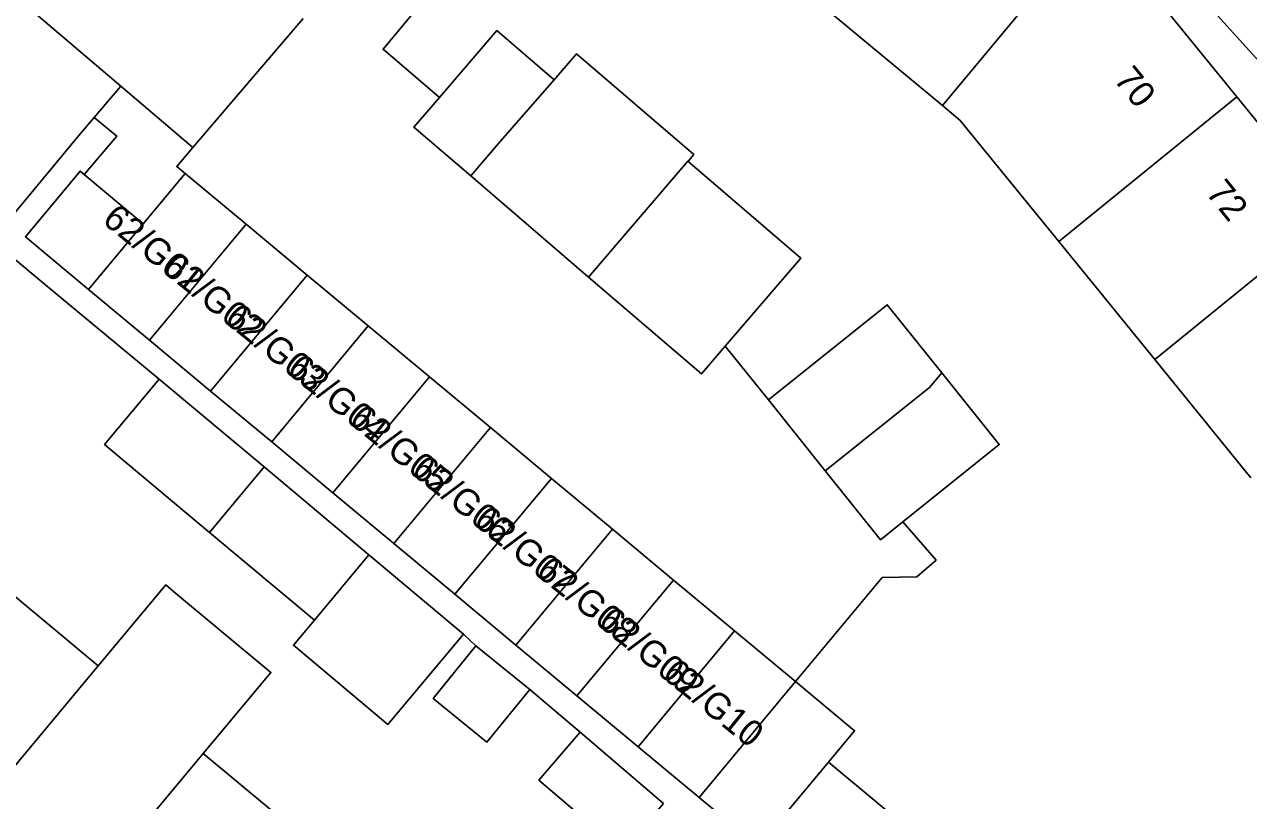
# Model space of a CAD drawing. Extents: x 162074 to 163034, y 381824 to 382557.
# Drawn here: x 162432.01 to 162478.91, y 381913.94 to 381943.68 of the extents above; entities that cross this region are included whole.
import ezdxf

# ---------------------------------------------------------------- set-up
doc = ezdxf.new("R2010")
doc.units = 0
for name, color, linetype in [('IMGEO_Pand', 7, 'Continuous'), ('IMGEO_Pand_nummerreeks', 7, 'Continuous'), ('IMGEO_Rijbaan_lokaal_open', 7, 'Continuous'), ('IMGEO_Voetpad_open', 7, 'Continuous')]:
    doc.layers.add(name, color=color, linetype=linetype)

msp = doc.modelspace()

# ---------------------------------------------------------------- linework, layer by layer
at = {"layer": 'IMGEO_Pand'}
for points in [[(162435.703, 381941.319), (162431.774, 381944.667), (162435.925, 381949.539)], [(162467.176, 381940.577), (162472.75, 381947.274)], [(162472.75, 381947.274), (162475.216, 381945.222), (162475.088, 381945.068), (162478.463, 381940.914)], [(162467.176, 381940.577), (162462.557, 381944.412)], [(162442.682, 381943.917), (162438.464, 381938.967)], [(162447.904, 381940.882), (162450.107, 381943.449), (162452.304, 381941.563)], [(162452.304, 381941.563), (162453.157, 381942.556), (162457.651, 381938.699), (162457.446, 381938.46), (162457.429, 381938.44)], [(162449.107, 381937.877), (162450.237, 381939.193), (162452.304, 381941.563)], [(162435.703, 381941.319), (162434.676, 381940.113)], [(162438.464, 381938.967), (162436.557, 381940.591), (162435.703, 381941.319)], [(162449.107, 381937.877), (162446.929, 381939.746), (162447.904, 381940.882)], [(162471.634, 381935.364), (162467.861, 381940.008), (162467.176, 381940.577)], [(162471.634, 381935.364), (162478.463, 381940.914)], [(162478.463, 381940.914), (162482.143, 381936.385)], [(162434.676, 381940.113), (162435.54, 381939.396), (162434.293, 381937.933)], [(162438.163, 381937.971), (162437.843, 381938.238), (162438.464, 381938.967)], [(162457.429, 381938.44), (162453.619, 381934.004)], [(162457.429, 381938.44), (162461.753, 381934.728), (162458.86, 381931.358)], [(162434.463, 381933.527), (162432.041, 381935.544), (162434.138, 381938.062), (162434.293, 381937.933)], [(162434.293, 381937.933), (162436.56, 381936.045)], [(162436.56, 381936.045), (162438.163, 381937.971)], [(162438.163, 381937.971), (162440.502, 381936.023)], [(162453.619, 381934.004), (162449.107, 381937.877)], [(162482.143, 381936.385), (162475.314, 381930.836)], [(162434.463, 381933.527), (162436.56, 381936.045)], [(162440.502, 381936.023), (162436.802, 381931.579)], [(162442.841, 381934.076), (162440.502, 381936.023)], [(162475.314, 381930.836), (162471.634, 381935.364)], [(162442.841, 381934.076), (162439.141, 381929.632)], [(162445.181, 381932.128), (162442.841, 381934.076)], [(162458.86, 381931.358), (162457.944, 381930.291), (162453.619, 381934.004)], [(162436.802, 381931.579), (162434.463, 381933.527)], [(162460.512, 381929.294), (162465.067, 381932.939), (162467.15, 381930.336)], [(162441.481, 381927.684), (162445.181, 381932.128)], [(162447.52, 381930.181), (162445.181, 381932.128)], [(162439.141, 381929.632), (162436.802, 381931.579)], [(162478.994, 381926.306), (162475.314, 381930.836)], [(162443.82, 381925.737), (162447.52, 381930.181)], [(162449.859, 381928.233), (162447.52, 381930.181)], [(162467.15, 381930.336), (162466.688, 381929.77), (162462.691, 381926.571)], [(162467.15, 381930.336), (162469.356, 381927.58), (162465.664, 381924.626)], [(162439.098, 381924.216), (162435.075, 381927.588), (162437.172, 381930.09)], [(162437.172, 381930.09), (162441.188, 381926.723)], [(162441.481, 381927.684), (162439.141, 381929.632)], [(162462.691, 381926.571), (162460.512, 381929.294)], [(162446.159, 381923.789), (162449.859, 381928.233)], [(162452.198, 381926.285), (162449.859, 381928.233)], [(162443.82, 381925.737), (162441.481, 381927.684)], [(162441.188, 381926.723), (162439.098, 381924.216)], [(162441.188, 381926.723), (162445.204, 381923.357)], [(162465.664, 381924.626), (162464.801, 381923.935), (162462.691, 381926.571)], [(162452.198, 381926.285), (162448.498, 381921.842)], [(162454.537, 381924.338), (162452.198, 381926.285)], [(162446.159, 381923.789), (162443.82, 381925.737)], [(162443.114, 381920.85), (162439.098, 381924.216)], [(162450.838, 381919.894), (162454.537, 381924.338)], [(162454.537, 381924.338), (162456.877, 381922.39)], [(162448.498, 381921.842), (162446.159, 381923.789)], [(162445.204, 381923.357), (162443.114, 381920.85)], [(162445.204, 381923.357), (162448.831, 381920.317)], [(162427.54, 381918.534), (162430.803, 381922.449), (162434.83, 381919.095)], [(162434.83, 381919.095), (162437.421, 381922.203), (162437.718, 381921.955), (162441.447, 381918.85), (162439.247, 381916.212), (162438.856, 381915.742)], [(162456.877, 381922.39), (162453.177, 381917.947)], [(162459.216, 381920.443), (162456.877, 381922.39)], [(162450.838, 381919.894), (162448.498, 381921.842)], [(162448.831, 381920.317), (162445.931, 381916.857), (162442.313, 381919.889), (162443.114, 381920.85)], [(162455.516, 381915.999), (162459.216, 381920.443)], [(162459.216, 381920.443), (162461.555, 381918.495)], [(162451.365, 381918.198), (162449.724, 381916.179), (162447.663, 381917.854), (162449.304, 381919.873)], [(162449.304, 381919.873), (162451.365, 381918.198)], [(162453.177, 381917.947), (162450.838, 381919.894)], [(162434.83, 381919.095), (162425.697, 381908.139)], [(162461.555, 381918.495), (162457.856, 381914.051)], [(162461.555, 381918.495), (162463.814, 381916.614), (162462.808, 381915.405)], [(162455.516, 381915.999), (162453.177, 381917.947)], [(162456.497, 381913.825), (162454.922, 381911.982), (162451.718, 381914.721), (162453.293, 381916.563)], [(162453.293, 381916.563), (162456.497, 381913.825)], [(162430.021, 381905.142), (162438.856, 381915.742)], [(162438.856, 381915.742), (162442.882, 381912.389), (162441.973, 381911.298)], [(162457.856, 381914.051), (162455.516, 381915.999)], [(162460.871, 381913.079), (162462.808, 381915.405)], [(162462.808, 381915.405), (162468.748, 381910.459)], [(162460.699, 381912.872), (162460.115, 381912.17), (162457.856, 381914.051)]]:
    msp.add_lwpolyline(points, dxfattribs=at)
at = {"layer": 'IMGEO_Rijbaan_lokaal_open'}
for points in [[(162453.434, 381951.988), (162445.748, 381942.733), (162447.904, 381940.882)], [(162458.86, 381931.358), (162460.512, 381929.294)], [(162465.664, 381924.626), (162466.937, 381923.157), (162466.195, 381922.514), (162464.872, 381922.48), (162461.555, 381918.495)]]:
    msp.add_lwpolyline(points, dxfattribs=at)
msp.add_arc((162415.641, 381887.258), 86.754, 39.9668, 48.2971, dxfattribs=at)
at = {"layer": 'IMGEO_Voetpad_open'}
for points in [[(162524.728, 381886.592), (162523.779, 381887.754), (162520.879, 381891.323), (162500, 381916.926), (162479.554, 381941.998), (162475.997, 381945.948)], [(162420.235, 381945.27), (162427.488, 381939.257), (162431.316, 381936.081), (162434.157, 381939.504), (162434.676, 381940.113)], [(162429.113, 381936.789), (162433.138, 381933.434), (162437.172, 381930.09)], [(162448.831, 381920.317), (162449.304, 381919.873)], [(162451.365, 381918.198), (162453.293, 381916.563)]]:
    msp.add_lwpolyline(points, dxfattribs=at)

# ---------------------------------------------------------------- texts
at = {"layer": 'IMGEO_Pand_nummerreeks'}
for s, rotation, p in [('70', 309.0947, (162473.711, 381941.562)), ('72', 309.0942, (162477.239, 381937.219)), ('62/G01', 320.9128, (162434.942, 381936.109)), ('62/G02', 320.9156, (162437.236, 381934.245)), ('62/G03', 320.9156, (162439.626, 381932.304)), ('62/G04', 320.9156, (162442.012, 381930.366)), ('62/G05', 320.9156, (162444.397, 381928.429)), ('62/G06', 320.9156, (162446.783, 381926.491)), ('62/G07', 320.9156, (162449.168, 381924.554)), ('62/G08', 320.9156, (162451.556, 381922.614)), ('62/G09', 320.9156, (162453.936, 381920.681)), ('62/G10', 320.9156, (162456.398, 381918.682))]:
    msp.add_text(s, height=1, rotation=rotation, dxfattribs=at).set_placement(p)

doc.saveas('drawing.dxf')
